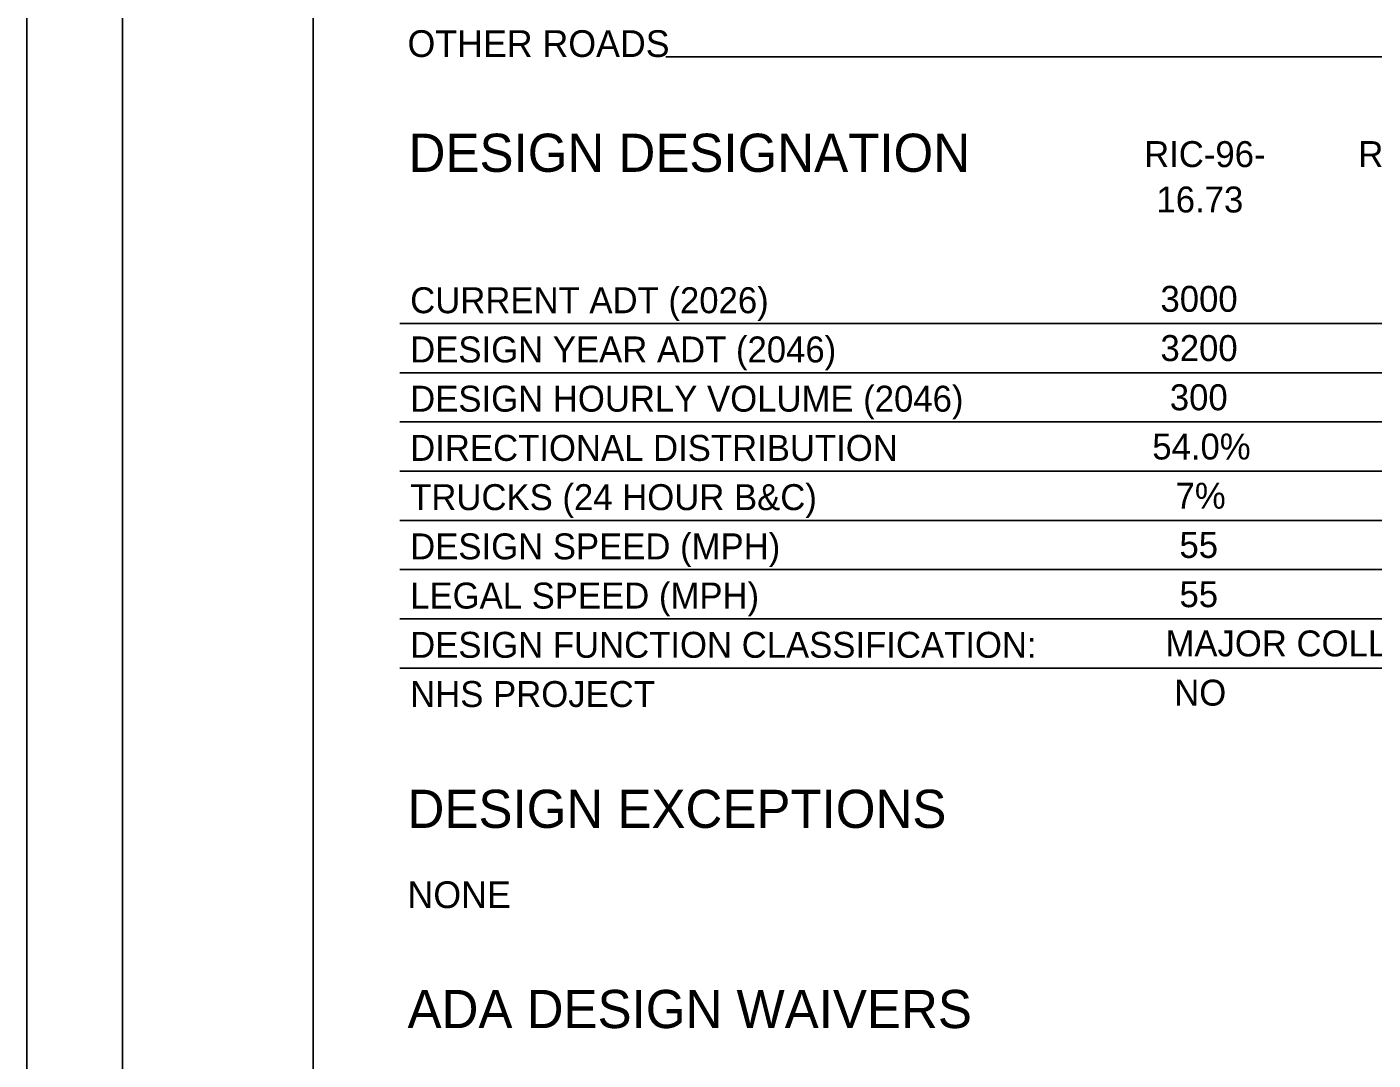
# Model space of a CAD drawing. Extents: x 0 to 70.2, y 0 to 31.4.
# Drawn here: x 0 to 7.05, y 5.62 to 11.03 of the extents above; entities that cross this region are included whole.
import ezdxf

# ---------------------------------------------------------------- set-up
doc = ezdxf.new("R2010")
doc.units = 0
for name, color, linetype in [('Default', 7, 'Continuous'), ('SH_Border', 7, 'Continuous'), ('SH_Cut_Line', 7, 'Continuous'), ('SH_Data', 7, 'Continuous'), ('SH_Text', 7, 'Continuous')]:
    doc.layers.add(name, color=color, linetype=linetype)

msp = doc.modelspace()

# ---------------------------------------------------------------- linework, layer by layer
at = {"layer": 'Default'}
for p, q in [((1.9545, 9.4804), (6.5648, 9.4804)), ((6.5648, 9.4804), (6.8764, 9.4804)), ((6.8764, 9.4804), (7.7362, 9.4804)), ((1.9545, 9.2225), (6.5648, 9.2225)), ((6.5648, 9.2225), (6.8764, 9.2225)), ((6.8764, 9.2225), (7.7362, 9.2225)), ((1.9545, 8.9645), (6.5648, 8.9645)), ((6.5648, 8.9645), (6.8764, 8.9645)), ((6.8764, 8.9645), (7.7362, 8.9645)), ((1.9545, 8.7066), (6.5648, 8.7066)), ((6.5648, 8.7066), (6.8764, 8.7066)), ((6.8764, 8.7066), (7.7362, 8.7066)), ((1.9545, 8.4487), (6.5648, 8.4487)), ((6.5648, 8.4487), (6.8764, 8.4487)), ((6.8764, 8.4487), (7.7362, 8.4487)), ((1.9545, 8.1908), (6.5648, 8.1908)), ((6.5648, 8.1908), (6.8764, 8.1908)), ((6.8764, 8.1908), (7.7362, 8.1908)), ((1.9545, 7.9329), (6.5648, 7.9329)), ((6.5648, 7.9329), (6.8764, 7.9329)), ((6.8764, 7.9329), (7.7362, 7.9329)), ((1.9545, 7.675), (6.5648, 7.675)), ((6.5648, 7.675), (6.8764, 7.675)), ((6.8764, 7.675), (7.7362, 7.675))]:
    msp.add_line(p, q, dxfattribs=at)
at = {"layer": 'SH_Border'}
for points in [[(0.5, 21.5), (1.5, 21.5), (1.5, 0.5), (0.5, 0.5)], [(1.5, 21.5), (33.5, 21.5), (33.5, 0.5), (1.5, 0.5)]]:
    msp.add_lwpolyline(points, close=True, dxfattribs=at)
at = {"layer": 'SH_Cut_Line'}
msp.add_lwpolyline([(0, 0), (34, 0), (34, 22), (0, 22)], close=True, dxfattribs=at)
at = {"layer": 'SH_Data'}
msp.add_line((7.7, 10.8767), (3.3471, 10.8767), dxfattribs=at)

# ---------------------------------------------------------------- texts
at = {"layer": 'Default'}
for s, height, p in [('RIC-96-', 0.13594, (5.854, 10.2997)), ('RIC-603-', 0.13594, (6.9765, 10.2997)), ('16.73', 0.13594, (5.9188, 10.0618)), ('CURRENT ADT (2026)', 0.135944, (2.0082, 9.5341)), ('3000', 0.13594, (5.9398, 9.5414)), ('DESIGN YEAR ADT (2046)', 0.135944, (2.0082, 9.2762)), ('3200', 0.13594, (5.9398, 9.2834)), ('DESIGN HOURLY VOLUME (2046)', 0.135944, (2.0082, 9.0183)), ('300', 0.13594, (5.9887, 9.0255)), ('DIRECTIONAL DISTRIBUTION', 0.135944, (2.0082, 8.7604)), ('54.0%', 0.13594, (5.8969, 8.7676)), ('TRUCKS (24 HOUR B&C)', 0.135944, (2.0082, 8.5024)), ('7%', 0.13594, (6.0189, 8.5097)), ('DESIGN SPEED (MPH)', 0.135944, (2.0082, 8.2445)), ('55', 0.13594, (6.0393, 8.2518)), ('LEGAL SPEED (MPH)', 0.135944, (2.0082, 7.9866)), ('55', 0.13594, (6.0393, 7.9939)), ('DESIGN FUNCTION CLASSIFICATION:', 0.135944, (2.0082, 7.7287)), ('MAJOR COLLECTOR', 0.135944, (5.9659, 7.7359)), ('NHS PROJECT', 0.135944, (2.0082, 7.4708)), ('NO', 0.13594, (6.0117, 7.478))]:
    msp.add_text(s, height=height, dxfattribs=at).set_placement(p)
at = {"layer": 'SH_Data'}
msp.add_text('DESIGN DESIGNATION', height=0.2, dxfattribs=at).set_placement((2, 10.2747))
at = {"layer": 'SH_Text'}
for s, height, p in [('OTHER ROADS', 0.14, (1.9944, 10.8767)), ('DESIGN EXCEPTIONS', 0.2, (1.9944, 6.8374)), ('NONE', 0.14, (1.9944, 6.4174)), ('ADA DESIGN WAIVERS', 0.2, (1.9944, 5.7886))]:
    msp.add_text(s, height=height, dxfattribs=at).set_placement(p)

doc.saveas('drawing.dxf')
